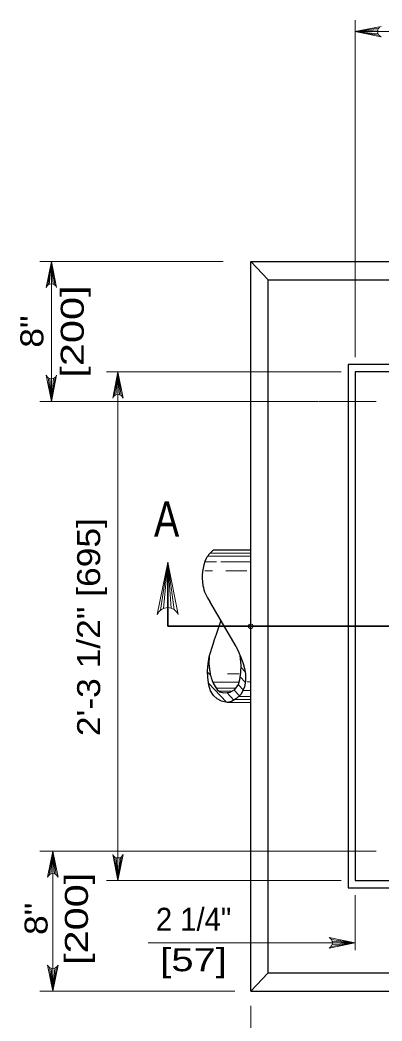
# Model space of a CAD drawing. Extents: x -410.5 to -376.5, y 1617.6 to 1661.6.
# Drawn here: x -396.34 to -393.89, y 1621.21 to 1628 of the extents above; entities that cross this region are included whole.
import ezdxf
from ezdxf.enums import TextEntityAlignment as Align

# ---------------------------------------------------------------- set-up
doc = ezdxf.new("R2010")
doc.units = 0
doc.header["$LTSCALE"] = 0.062
doc.header["$PDMODE"] = 32
doc.header["$PDSIZE"] = 0.031
doc.layers.add('1', color=7, linetype='Continuous', lineweight=13)

msp = doc.modelspace()

# ---------------------------------------------------------------- linework, layer by layer
at = {"layer": '1'}
for p, q in [((-394.06925, 1625.71183), (-394.06925, 1627.99733)), ((-393.9105, 1627.94108), (-394.07075, 1627.91867)), ((-393.91592, 1627.93), (-394.07075, 1627.91867)), ((-394.07075, 1627.91867), (-392.13725, 1627.91867)), ((-393.91758, 1627.91867), (-394.07075, 1627.91867)), ((-393.91475, 1627.90425), (-394.07075, 1627.91867)), ((-393.90858, 1627.89392), (-394.07075, 1627.91867)), ((-394.96392, 1626.3615), (-396.20775, 1626.3615)), ((-396.15392, 1626.19933), (-396.12908, 1626.3615)), ((-396.1435, 1626.2055), (-396.12908, 1626.3615)), ((-396.12908, 1626.3615), (-396.12908, 1625.41208)), ((-396.12908, 1626.20833), (-396.12908, 1626.3615)), ((-396.11775, 1626.20667), (-396.12908, 1626.3615)), ((-396.10667, 1626.20125), (-396.12908, 1626.3615)), ((-394.16367, 1625.61192), (-395.75675, 1625.61192)), ((-395.70283, 1625.44983), (-395.67808, 1625.61192)), ((-395.69242, 1625.45592), (-395.67808, 1625.61192)), ((-395.67808, 1625.61192), (-395.67808, 1622.16392)), ((-395.67808, 1625.45875), (-395.67808, 1625.61192)), ((-395.66675, 1625.45708), (-395.67808, 1625.61192)), ((-395.65558, 1625.45167), (-395.67808, 1625.61192)), ((-396.1515, 1625.57233), (-396.12908, 1625.41208)), ((-396.14042, 1625.56683), (-396.12908, 1625.41208)), ((-396.10433, 1625.57417), (-396.12908, 1625.41208)), ((-396.11475, 1625.56808), (-396.12908, 1625.41208)), ((-396.12908, 1625.56525), (-396.12908, 1625.41208)), ((-394.317, 1625.41208), (-396.20775, 1625.41208)), ((-393.92767, 1625.41208), (-394.31317, 1625.41208)), ((-395.00933, 1624.324), (-395.08858, 1624.324)), ((-394.77725, 1624.364), (-395.06875, 1624.364)), ((-394.77725, 1624.384), (-395.0525, 1624.384)), ((-394.77725, 1624.324), (-394.98117, 1624.324)), ((-395.39008, 1623.99633), (-395.3405, 1624.32058)), ((-395.36933, 1624.00858), (-395.3405, 1624.32058)), ((-395.3405, 1624.01425), (-395.3405, 1624.32058)), ((-395.31783, 1624.011), (-395.3405, 1624.32058)), ((-395.29567, 1624.00008), (-395.3405, 1624.32058)), ((-395.0375, 1624.26408), (-395.08858, 1624.26408)), ((-394.80308, 1624.26408), (-394.94692, 1624.26408)), ((-395.05933, 1623.66358), (-395.06125, 1623.66558)), ((-394.84783, 1623.686), (-394.84867, 1623.68692)), ((-394.84475, 1623.6775), (-394.84817, 1623.68117)), ((-395.04992, 1623.5555), (-395.06975, 1623.57642)), ((-395.06075, 1623.63483), (-395.06583, 1623.64017)), ((-395.06083, 1623.63692), (-395.0655, 1623.64192)), ((-394.81608, 1623.57925), (-394.84283, 1623.60767)), ((-394.85558, 1623.508), (-395.03517, 1623.508)), ((-394.85683, 1623.56458), (-394.93592, 1623.56458)), ((-394.81458, 1623.50983), (-394.84792, 1623.54508)), ((-394.77725, 1623.51183), (-394.8015, 1623.51183)), ((-394.9415, 1623.373), (-395.06392, 1623.5025)), ((-394.87742, 1623.468), (-395.01067, 1623.468)), ((-394.90208, 1623.448), (-394.99117, 1623.448)), ((-394.8545, 1623.41642), (-394.8905, 1623.45467)), ((-394.82908, 1623.45742), (-394.861, 1623.49117)), ((-394.77725, 1623.45183), (-394.83167, 1623.45183)), ((-394.89133, 1623.38767), (-394.939, 1623.438)), ((-394.77725, 1623.37192), (-394.93633, 1623.37192)), ((-394.77725, 1623.39192), (-394.88367, 1623.39192)), ((-394.77725, 1623.41183), (-394.85908, 1623.41183)), ((-394.29908, 1622.36383), (-396.20775, 1622.36383)), ((-396.14458, 1622.20167), (-396.11975, 1622.36383)), ((-396.13417, 1622.20783), (-396.11975, 1622.36383)), ((-396.11975, 1621.41433), (-396.11975, 1622.36383)), ((-396.11975, 1622.21067), (-396.11975, 1622.36383)), ((-396.10842, 1622.209), (-396.11975, 1622.36383)), ((-396.09733, 1622.20358), (-396.11975, 1622.36383)), ((-393.92767, 1622.36383), (-394.29908, 1622.36383)), ((-395.7005, 1622.32417), (-395.67808, 1622.16392)), ((-395.68933, 1622.31875), (-395.67808, 1622.16392)), ((-395.65325, 1622.32608), (-395.67808, 1622.16392)), ((-395.66367, 1622.31992), (-395.67808, 1622.16392)), ((-395.67808, 1622.31708), (-395.67808, 1622.16392)), ((-394.16367, 1622.16392), (-395.75675, 1622.16392)), ((-394.06925, 1622.064), (-394.06925, 1621.69217)), ((-394.2295, 1621.7645), (-394.06925, 1621.74208)), ((-394.22408, 1621.75342), (-394.06925, 1621.74208)), ((-394.06925, 1621.74208), (-395.47258, 1621.74208)), ((-394.23142, 1621.71733), (-394.06925, 1621.74208)), ((-394.22525, 1621.72767), (-394.06925, 1621.74208)), ((-394.22242, 1621.74208), (-394.06925, 1621.74208)), ((-396.14217, 1621.57458), (-396.11975, 1621.41433)), ((-396.13108, 1621.56917), (-396.11975, 1621.41433)), ((-396.095, 1621.5765), (-396.11975, 1621.41433)), ((-396.10542, 1621.57033), (-396.11975, 1621.41433)), ((-396.11975, 1621.5675), (-396.11975, 1621.41433)), ((-394.8845, 1621.41433), (-396.20775, 1621.41433)), ((-394.77725, 1621.31492), (-394.77725, 1620.696))]:
    msp.add_line(p, q, dxfattribs=at)
at = {"layer": '1', "lineweight": 25}
for p, q in [((-394.77725, 1626.3615), (-394.65925, 1626.23658)), ((-394.65925, 1621.53925), (-394.65925, 1626.23658)), ((-394.65925, 1626.23658), (-390.26967, 1626.23658)), ((-394.06925, 1625.61192), (-394.06925, 1622.16392)), ((-390.85967, 1625.61192), (-394.06925, 1625.61192)), ((-394.77725, 1624.404), (-395.03008, 1624.404)), ((-394.87625, 1623.74983), (-395.05542, 1624.05633)), ((-394.06925, 1622.16392), (-390.85967, 1622.164)), ((-394.65925, 1621.53925), (-394.77725, 1621.41433)), ((-394.65925, 1621.53925), (-390.26967, 1621.53933)), ((-394.77725, 1621.41433), (-390.15167, 1621.41442))]:
    msp.add_line(p, q, dxfattribs=at)
at = {"layer": '1', "lineweight": 35}
for q in [(-395.3405, 1624.32058), (-391.70058, 1623.88792)]:
    msp.add_line((-395.3405, 1623.88792), q, dxfattribs=at)
at = {"layer": '1'}
for points in [[(-393.89375, 1627.88325), (-394.07075, 1627.91867), (-393.89375, 1627.95408)], [(-396.1645, 1626.1845), (-396.12908, 1626.3615), (-396.09375, 1626.1845)], [(-395.71342, 1625.43492), (-395.67808, 1625.61192), (-395.64267, 1625.43492)], [(-396.09375, 1625.58908), (-396.12908, 1625.41208), (-396.1645, 1625.58908)], [(-395.41133, 1623.96658), (-395.3405, 1624.32058), (-395.26975, 1623.96658)], [(-396.15517, 1622.18683), (-396.11975, 1622.36383), (-396.08433, 1622.18683)], [(-395.64267, 1622.34092), (-395.67808, 1622.16392), (-395.71342, 1622.34092)], [(-394.24625, 1621.70667), (-394.06925, 1621.74208), (-394.24625, 1621.7775)], [(-396.08433, 1621.59133), (-396.11975, 1621.41433), (-396.15517, 1621.59133)]]:
    msp.add_lwpolyline(points, dxfattribs=at)
at = {"layer": '1', "lineweight": 25}
for points in [[(-394.77725, 1621.41433), (-394.77725, 1626.3615), (-390.15167, 1626.3615)], [(-394.84883, 1623.68883), (-394.82933, 1623.63592), (-394.81967, 1623.60133), (-394.8135, 1623.56433), (-394.81367, 1623.51483), (-394.82, 1623.47708), (-394.84275, 1623.428), (-394.87367, 1623.39742), (-394.90817, 1623.37825), (-394.93633, 1623.37192), (-394.97658, 1623.37967), (-395.00433, 1623.396), (-395.03, 1623.41825), (-395.04942, 1623.44958), (-395.06225, 1623.48908), (-395.06875, 1623.54033), (-395.07008, 1623.58625), (-395.06708, 1623.63333), (-395.05842, 1623.68075)], [(-394.84883, 1623.68883), (-394.82933, 1623.63592), (-394.81967, 1623.60133), (-394.8135, 1623.56433), (-394.81367, 1623.51483), (-394.82, 1623.47708), (-394.84275, 1623.428), (-394.87367, 1623.39742), (-394.90817, 1623.37825), (-394.93633, 1623.37192), (-394.97658, 1623.37967), (-395.00433, 1623.396), (-395.03, 1623.41825), (-395.04942, 1623.44958), (-395.06225, 1623.48908), (-395.06875, 1623.54033), (-395.07008, 1623.58625), (-395.06708, 1623.63333), (-395.05842, 1623.68075)], [(-395.05842, 1623.68075), (-395.06092, 1623.63608), (-395.05717, 1623.59642), (-395.05275, 1623.56608), (-395.04542, 1623.53892), (-395.03292, 1623.50158), (-395.019, 1623.479), (-395.00433, 1623.4595), (-394.98667, 1623.444), (-394.96025, 1623.43617), (-394.91617, 1623.44), (-394.8845, 1623.458), (-394.85958, 1623.493), (-394.85075, 1623.52642), (-394.84342, 1623.57383), (-394.84267, 1623.62292), (-394.84883, 1623.68883)], [(-395.05842, 1623.68075), (-395.06092, 1623.63608), (-395.05717, 1623.59642), (-395.05275, 1623.56608), (-395.04542, 1623.53892), (-395.03292, 1623.50158), (-395.019, 1623.479), (-395.00433, 1623.4595), (-394.98667, 1623.444), (-394.96025, 1623.43617), (-394.91617, 1623.44), (-394.8845, 1623.458), (-394.85958, 1623.493), (-394.85075, 1623.52642), (-394.84342, 1623.57383), (-394.84267, 1623.62292), (-394.84883, 1623.68883)]]:
    msp.add_lwpolyline(points, dxfattribs=at)
msp.add_lwpolyline([(-394.1165, 1622.11392), (-390.8125, 1622.114), (-390.8125, 1625.66192), (-394.1165, 1625.66192)], close=True, dxfattribs=at)
at = {"layer": '1'}
for centre, radius, start, end in [((-393.87942, 1627.91873), 0.0382, 112.08782, 247.91395), ((-396.12907, 1626.17021), 0.0382, 22.08782, 157.91395), ((-396.12915, 1625.60334), 0.0382, 202.08782, 337.91395), ((-395.678, 1625.42063), 0.0382, 22.08782, 157.91395), ((-395.34043, 1623.938), 0.0764, 22.08782, 157.91395), ((-395.67808, 1622.35521), 0.0382, 202.08782, 337.91395), ((-396.11973, 1622.17251), 0.0382, 22.08782, 157.91395), ((-394.26056, 1621.74214), 0.0382, 292.08605, 67.91218), ((-396.11981, 1621.60564), 0.0382, 202.08782, 337.91395)]:
    msp.add_arc(centre, radius, start, end, dxfattribs=at)
at = {"layer": '1', "lineweight": 25}
for centre, major_axis, start_param, end_param in [((-394.93629, 1624.26146), (0, 0.17367), 0.608535, 1.0523476), ((-394.83509, 1624.21985), (0, 0.28786), 1.1112416, 1.7626188), ((-394.86102, 1624.21536), (0, 0.26008), 1.7657992, 2.2285353)]:
    msp.add_ellipse(centre, major_axis=major_axis, ratio=0.944543, start_param=start_param, end_param=end_param, dxfattribs=at)
for points in [[(-395.05842, 1623.68075), (-395.04833, 1623.72192), (-395.02725, 1623.78817), (-394.97942, 1623.92267)], [(-394.87625, 1623.74983), (-394.86542, 1623.72733), (-394.85642, 1623.707), (-394.84883, 1623.68883)]]:
    msp.add_open_spline(points, degree=3, dxfattribs=at)
at = {"layer": '1'}
msp.add_point((-394.77725, 1623.88792), dxfattribs=at)

# ---------------------------------------------------------------- texts
for s, width, p in [('[200]', 1.35, (-395.90992, 1625.88542)), ('8"', 1.15, (-396.18392, 1625.88542)), ('[200]', 1.35, (-395.88142, 1621.90442)), ('8"', 1.15, (-396.15542, 1621.90442))]:
    msp.add_text(s, height=0.156, rotation=90, dxfattribs=dict(at, width=width)).set_placement(p, align=Align.CENTER)
for s, height, width, p in [('A', 0.24, 0.8, (-395.34775, 1624.49533)), ('2 1/4"', 0.156, 0.95, (-395.16504, 1621.82333)), ('[57]', 0.156, 1.3, (-395.16504, 1621.54933))]:
    msp.add_text(s, height=height, dxfattribs=dict(at, width=width)).set_placement(p, align=Align.CENTER)
at = {"layer": '1', "width": 1.15}
msp.add_text('2\'-3 1/2" [695]', height=0.156, rotation=90, dxfattribs=at).set_placement((-395.79867, 1623.143))

doc.saveas('drawing.dxf')
